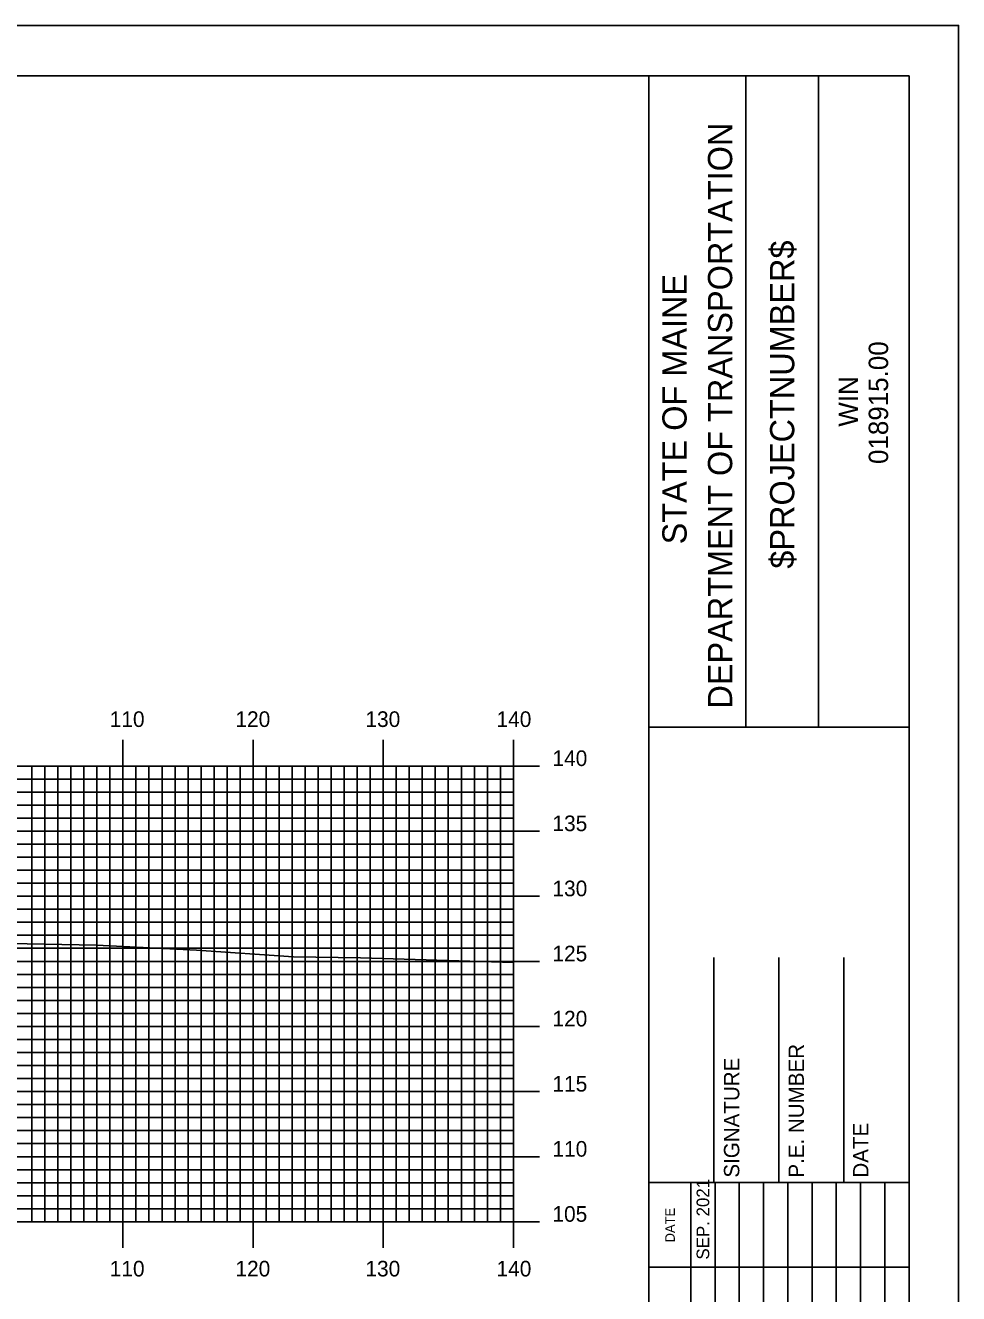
# Model space of a CAD drawing. Extents: x 1767694 to 1768037, y 442591 to 442811.
# Drawn here: x 1767961.9 to 1768033.7, y 442713.1 to 442810.5 of the extents above; entities that cross this region are included whole.
import ezdxf

# ---------------------------------------------------------------- set-up
doc = ezdxf.new("R2010")
doc.units = 0
for name, color, linetype in [('BORDER', 7, 'Continuous'), ('H_V ANNOTATION', 7, 'Continuous'), ('MAJOR', 7, 'Continuous'), ('MINOR', 7, 'Continuous'), ('PLOT BOUNDARY', 7, 'Continuous'), ('S_Roadway_Centerline', 7, 'Continuous')]:
    doc.layers.add(name, color=color, linetype=linetype)

msp = doc.modelspace()

# ---------------------------------------------------------------- linework, layer by layer
at = {"layer": 'BORDER'}
for p, q in [((1768009.85, 442596.665), (1768009.85, 442806.665)), ((1768017.307, 442756.659), (1768017.307, 442806.659)), ((1768022.897, 442756.659), (1768022.897, 442806.659)), ((1768009.851, 442756.653), (1768029.85, 442756.653)), ((1768014.85, 442721.671), (1768014.85, 442738.966)), ((1768019.85, 442721.671), (1768019.85, 442738.966)), ((1768024.85, 442721.671), (1768024.85, 442738.966)), ((1768009.85, 442721.671), (1768029.85, 442721.671))]:
    msp.add_line(p, q, dxfattribs=at)
msp.add_lwpolyline([(1767709.85, 442596.665), (1768029.85, 442596.665), (1768029.85, 442806.665), (1767709.85, 442806.665)], close=True, dxfattribs=at)
for points in [[(1768013.079, 442715.171), (1768013.079, 442721.671)], [(1768014.944, 442686.677), (1768014.944, 442721.671)], [(1768016.808, 442721.671), (1768016.808, 442686.677)], [(1768018.671, 442686.677), (1768018.671, 442721.671)], [(1768020.535, 442686.677), (1768020.535, 442721.671)], [(1768022.398, 442686.677), (1768022.398, 442721.671)], [(1768024.261, 442686.677), (1768024.261, 442721.671)], [(1768026.125, 442686.677), (1768026.125, 442721.671)], [(1768027.988, 442686.677), (1768027.988, 442721.671)], [(1768013.081, 442686.677), (1768013.081, 442720.259)], [(1768009.85, 442715.171), (1768029.85, 442715.171)]]:
    msp.add_lwpolyline(points, dxfattribs=at)
at = {"layer": 'MAJOR'}
for p, q in [((1767969.45, 442755.669), (1767969.45, 442753.665)), ((1767979.45, 442755.669), (1767979.45, 442753.665)), ((1767989.45, 442755.669), (1767989.45, 442753.665)), ((1767999.45, 442755.669), (1767999.45, 442753.665)), ((1767719.45, 442753.665), (1767999.45, 442753.665)), ((1767719.45, 442753.665), (1767999.45, 442753.665)), ((1767969.45, 442718.665), (1767969.45, 442753.665)), ((1767979.45, 442718.665), (1767979.45, 442753.665)), ((1767989.45, 442718.665), (1767989.45, 442753.665)), ((1768001.454, 442753.665), (1767997.446, 442753.665)), ((1767999.45, 442718.665), (1767999.45, 442753.665)), ((1767999.45, 442718.665), (1767999.45, 442753.665)), ((1767719.45, 442748.665), (1767999.45, 442748.665)), ((1768001.454, 442748.665), (1767997.446, 442748.665)), ((1767719.45, 442743.665), (1767999.45, 442743.665)), ((1768001.454, 442743.665), (1767997.446, 442743.665)), ((1767719.45, 442738.665), (1767999.45, 442738.665)), ((1768001.454, 442738.665), (1767997.446, 442738.665)), ((1767719.45, 442733.665), (1767999.45, 442733.665)), ((1768001.454, 442733.665), (1767997.446, 442733.665)), ((1767719.45, 442728.665), (1767999.45, 442728.665)), ((1768001.454, 442728.665), (1767997.446, 442728.665)), ((1767719.45, 442723.665), (1767999.45, 442723.665)), ((1768001.454, 442723.665), (1767997.446, 442723.665)), ((1767719.45, 442718.665), (1767999.45, 442718.665)), ((1767719.45, 442718.665), (1767999.45, 442718.665)), ((1767969.45, 442716.661), (1767969.45, 442718.665)), ((1767979.45, 442716.661), (1767979.45, 442718.665)), ((1767989.45, 442716.661), (1767989.45, 442718.665)), ((1768001.454, 442718.665), (1767997.446, 442718.665)), ((1767999.45, 442716.661), (1767999.45, 442718.665))]:
    msp.add_line(p, q, dxfattribs=at)
at = {"layer": 'MINOR'}
for p, q in [((1767962.45, 442718.665), (1767962.45, 442753.665)), ((1767963.45, 442718.665), (1767963.45, 442753.665)), ((1767964.45, 442718.665), (1767964.45, 442753.665)), ((1767965.45, 442718.665), (1767965.45, 442753.665)), ((1767966.45, 442718.665), (1767966.45, 442753.665)), ((1767967.45, 442718.665), (1767967.45, 442753.665)), ((1767968.45, 442718.665), (1767968.45, 442753.665)), ((1767970.45, 442718.665), (1767970.45, 442753.665)), ((1767971.45, 442718.665), (1767971.45, 442753.665)), ((1767972.45, 442718.665), (1767972.45, 442753.665)), ((1767973.45, 442718.665), (1767973.45, 442753.665)), ((1767974.45, 442718.665), (1767974.45, 442753.665)), ((1767975.45, 442718.665), (1767975.45, 442753.665)), ((1767976.45, 442718.665), (1767976.45, 442753.665)), ((1767977.45, 442718.665), (1767977.45, 442753.665)), ((1767978.45, 442718.665), (1767978.45, 442753.665)), ((1767980.45, 442718.665), (1767980.45, 442753.665)), ((1767981.45, 442718.665), (1767981.45, 442753.665)), ((1767982.45, 442718.665), (1767982.45, 442753.665)), ((1767983.45, 442718.665), (1767983.45, 442753.665)), ((1767984.45, 442718.665), (1767984.45, 442753.665)), ((1767985.45, 442718.665), (1767985.45, 442753.665)), ((1767986.45, 442718.665), (1767986.45, 442753.665)), ((1767987.45, 442718.665), (1767987.45, 442753.665)), ((1767988.45, 442718.665), (1767988.45, 442753.665)), ((1767990.45, 442718.665), (1767990.45, 442753.665)), ((1767991.45, 442718.665), (1767991.45, 442753.665)), ((1767992.45, 442718.665), (1767992.45, 442753.665)), ((1767993.45, 442718.665), (1767993.45, 442753.665)), ((1767994.45, 442718.665), (1767994.45, 442753.665)), ((1767995.45, 442718.665), (1767995.45, 442753.665)), ((1767996.45, 442718.665), (1767996.45, 442753.665)), ((1767997.45, 442718.665), (1767997.45, 442753.665)), ((1767998.45, 442718.665), (1767998.45, 442753.665)), ((1767719.45, 442752.665), (1767999.45, 442752.665)), ((1767999.45, 442752.665), (1767997.446, 442752.665)), ((1767719.45, 442751.665), (1767999.45, 442751.665)), ((1767999.45, 442751.665), (1767997.446, 442751.665)), ((1767719.45, 442750.665), (1767999.45, 442750.665)), ((1767999.45, 442750.665), (1767997.446, 442750.665)), ((1767719.45, 442749.665), (1767999.45, 442749.665)), ((1767999.45, 442749.665), (1767997.446, 442749.665)), ((1767719.45, 442747.665), (1767999.45, 442747.665)), ((1767999.45, 442747.665), (1767997.446, 442747.665)), ((1767719.45, 442746.665), (1767999.45, 442746.665)), ((1767999.45, 442746.665), (1767997.446, 442746.665)), ((1767719.45, 442745.665), (1767999.45, 442745.665)), ((1767999.45, 442745.665), (1767997.446, 442745.665)), ((1767719.45, 442744.665), (1767999.45, 442744.665)), ((1767999.45, 442744.665), (1767997.446, 442744.665)), ((1767719.45, 442742.665), (1767999.45, 442742.665)), ((1767999.45, 442742.665), (1767997.446, 442742.665)), ((1767719.45, 442741.665), (1767999.45, 442741.665)), ((1767999.45, 442741.665), (1767997.446, 442741.665)), ((1767719.45, 442740.665), (1767999.45, 442740.665)), ((1767999.45, 442740.665), (1767997.446, 442740.665)), ((1767719.45, 442739.665), (1767999.45, 442739.665)), ((1767999.45, 442739.665), (1767997.446, 442739.665)), ((1767719.45, 442737.665), (1767999.45, 442737.665)), ((1767999.45, 442737.665), (1767997.446, 442737.665)), ((1767719.45, 442736.665), (1767999.45, 442736.665)), ((1767999.45, 442736.665), (1767997.446, 442736.665)), ((1767719.45, 442735.665), (1767999.45, 442735.665)), ((1767999.45, 442735.665), (1767997.446, 442735.665)), ((1767719.45, 442734.665), (1767999.45, 442734.665)), ((1767999.45, 442734.665), (1767997.446, 442734.665)), ((1767719.45, 442732.665), (1767999.45, 442732.665)), ((1767999.45, 442732.665), (1767997.446, 442732.665)), ((1767719.45, 442731.665), (1767999.45, 442731.665)), ((1767999.45, 442731.665), (1767997.446, 442731.665)), ((1767719.45, 442730.665), (1767999.45, 442730.665)), ((1767999.45, 442730.665), (1767997.446, 442730.665)), ((1767719.45, 442729.665), (1767999.45, 442729.665)), ((1767999.45, 442729.665), (1767997.446, 442729.665)), ((1767719.45, 442727.665), (1767999.45, 442727.665)), ((1767999.45, 442727.665), (1767997.446, 442727.665)), ((1767719.45, 442726.665), (1767999.45, 442726.665)), ((1767999.45, 442726.665), (1767997.446, 442726.665)), ((1767719.45, 442725.665), (1767999.45, 442725.665)), ((1767999.45, 442725.665), (1767997.446, 442725.665)), ((1767719.45, 442724.665), (1767999.45, 442724.665)), ((1767999.45, 442724.665), (1767997.446, 442724.665)), ((1767719.45, 442722.665), (1767999.45, 442722.665)), ((1767999.45, 442722.665), (1767997.446, 442722.665)), ((1767719.45, 442721.665), (1767999.45, 442721.665)), ((1767999.45, 442721.665), (1767997.446, 442721.665)), ((1767719.45, 442720.665), (1767999.45, 442720.665)), ((1767999.45, 442720.665), (1767997.446, 442720.665)), ((1767719.45, 442719.665), (1767999.45, 442719.665)), ((1767999.45, 442719.665), (1767997.446, 442719.665))]:
    msp.add_line(p, q, dxfattribs=at)
at = {"layer": 'PLOT BOUNDARY'}
msp.add_lwpolyline([(1767693.663, 442590.547), (1768033.663, 442590.547), (1768033.663, 442810.547), (1767693.663, 442810.547)], close=True, dxfattribs=at)
at = {"layer": 'S_Roadway_Centerline'}
msp.add_lwpolyline([(1767875.146, 442746.389), (1767891.751, 442746.451), (1767899.097, 442746.279), (1767911.166, 442745.693), (1767911.198, 442745.692), (1767911.252, 442745.687), (1767923.487, 442744.636), (1767930.858, 442743.315), (1767943.489, 442740.979), (1767949.442, 442740.15), (1767956.744, 442740.109), (1767967.425, 442739.897), (1767975.094, 442739.517), (1767982.566, 442739.022), (1767987.71, 442738.935), (1767999.45, 442738.58)], dxfattribs=at)

# ---------------------------------------------------------------- texts
at = {"layer": 'BORDER'}
for s, height, p in [('DEPARTMENT OF TRANSPORTATION', 1.86351, (1768016.263, 442758.077)), ('$PROJECTNUMBER$', 1.86351, (1768021.033, 442768.823)), ('STATE OF MAINE', 1.86351, (1768012.76, 442770.689)), ('018915.00', 1.4905, (1768028.241, 442776.861)), ('WIN', 1.4905, (1768025.923, 442779.725)), ('P.E. NUMBER', 1.1811, (1768021.771, 442722.055)), ('SIGNATURE', 1.1811, (1768016.81, 442722.055)), ('DATE', 1.1811, (1768026.732, 442722.055)), ('SEP. 2021', 0.9691, (1768014.496, 442715.762)), ('DATE', 0.7428, (1768011.858, 442717.083))]:
    msp.add_text(s, height=height, rotation=90, dxfattribs=at).set_placement(p)
at = {"layer": 'H_V ANNOTATION'}
for s, p in [('110', (1767968.433, 442756.665)), ('120', (1767978.09, 442756.665)), ('130', (1767988.079, 442756.665)), ('140', (1767998.154, 442756.665)), ('140', (1768002.45, 442753.665)), ('135', (1768002.45, 442748.665)), ('130', (1768002.45, 442743.665)), ('125', (1768002.45, 442738.665)), ('120', (1768002.45, 442733.665)), ('115', (1768002.45, 442728.665)), ('110', (1768002.45, 442723.665)), ('105', (1768002.45, 442718.665)), ('110', (1767968.433, 442714.465)), ('120', (1767978.09, 442714.465)), ('130', (1767988.079, 442714.465)), ('140', (1767998.154, 442714.465))]:
    msp.add_text(s, height=1.2, dxfattribs=at).set_placement(p)

doc.saveas('drawing.dxf')
